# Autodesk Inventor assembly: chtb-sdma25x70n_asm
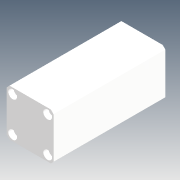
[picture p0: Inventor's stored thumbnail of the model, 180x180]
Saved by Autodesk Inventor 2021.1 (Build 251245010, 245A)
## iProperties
Company: Microsoft
Created: 2018-05
Part Number: chtb-sdma25x70n_asm
Description: STEP AP214
Document SubType Name: Assembly
Designer: user
Title: chtb-sdma25x70n_asm.STEP
Author: Windows
Revision Number: ÈÎºÎ
Sending System: SolidWorks 2015
Preprocessor: SwSTEP 2.0
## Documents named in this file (4)
- D:\Vault_2016\Projekty\Clamptek\Hydraulic\CHTB\CHTB-25\Inventor\chtb-sdma25x70n\chtb-sdma25x70n_asm.iam
- D:\Vault_2016\Projekty\Clamptek\Hydraulic\CHTB\CHTB-25\Inventor\chtb-sdma25x70n\CHTB-25QG.ipt
- D:\Vault_2016\Projekty\Clamptek\Hydraulic\CHTB\CHTB-25\Inventor\chtb-sdma25x70n\CHTB-SDMA25X70NBT.ipt
- D:\Vault_2016\Projekty\Clamptek\Hydraulic\CHTB\CHTB-25\Inventor\chtb-sdma25x70n\CHTB-SDMA25X70NHSG.ipt
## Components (3 placed, 3 different names)
1. CHTB-25QG_1
2. CHTB-SDMA25X70NBT_2
3. CHTB-SDMA25X70NHSG_3
